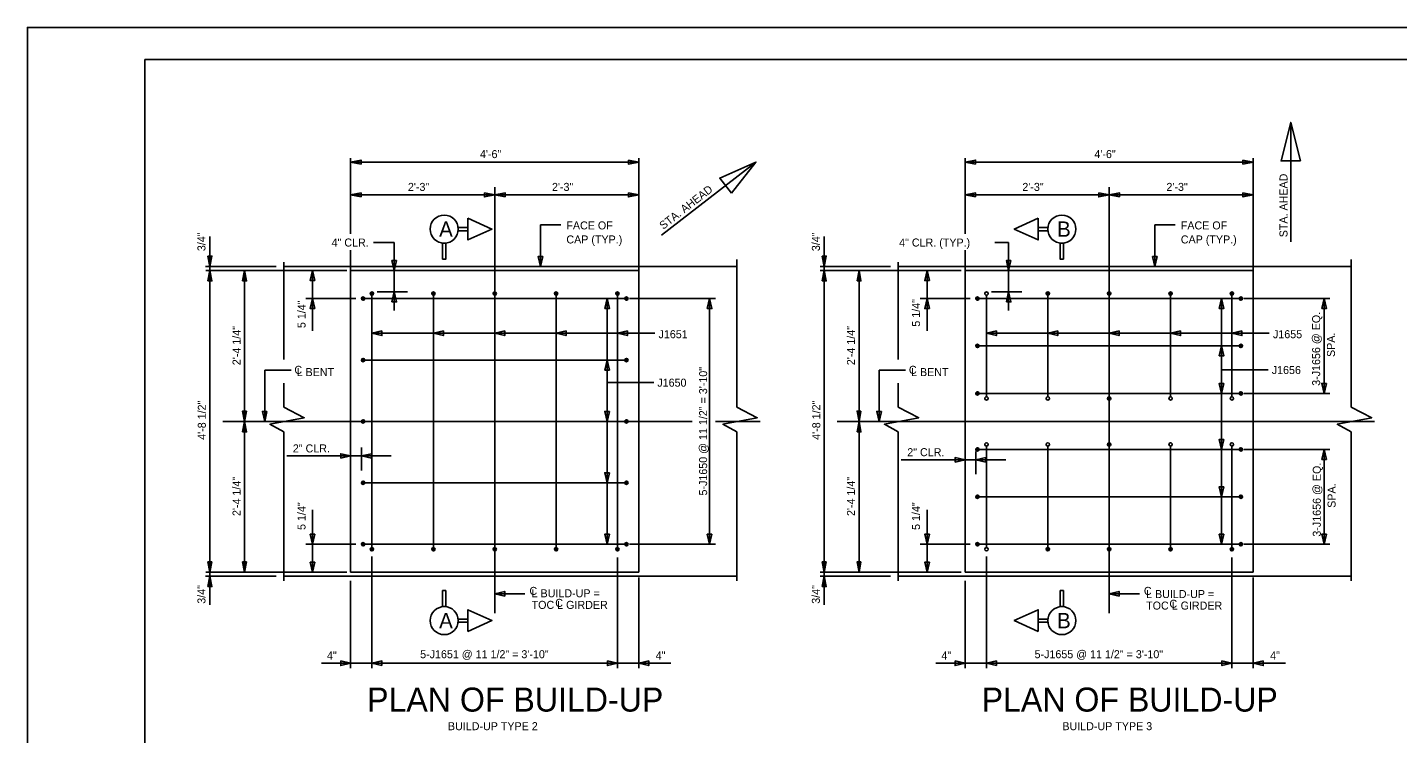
# Model space of a CAD drawing. Extents: x 1970675.2 to 1970711.3, y 796145.2 to 796167.2.
# Drawn here: x 1970675.24 to 1970696.64, y 796156.23 to 796167.25 of the extents above; entities that cross this region are included whole.
import ezdxf

# ---------------------------------------------------------------- set-up
doc = ezdxf.new("R2010")
doc.units = 0
for name, color, linetype in [('BR_AUTO DIMENSION', 7, 'Continuous'), ('BR_BORDER LINES', 7, 'Continuous'), ('BR_CENTER LINES', 7, 'Continuous'), ('BR_CONCRETE', 7, 'Continuous'), ('BR_REBAR', 7, 'Continuous'), ('BR_TEXT', 7, 'Continuous'), ('Default', 7, 'Continuous'), ('Level 31', 7, 'Continuous')]:
    doc.layers.add(name, color=color, linetype=linetype)

msp = doc.modelspace()

# ---------------------------------------------------------------- linework, layer by layer
at = {"layer": 'BR_AUTO DIMENSION'}
for p, q in [((1970694.967, 796165.764), (1970694.967, 796163.9)), ((1970680.285, 796164.025), (1970680.285, 796165.207)), ((1970680.285, 796165.145), (1970684.785, 796165.145)), ((1970684.785, 796163.452), (1970684.785, 796165.207)), ((1970686.613, 796165.146), (1970685.142, 796164.002)), ((1970689.881, 796164.025), (1970689.881, 796165.207)), ((1970689.881, 796165.145), (1970694.381, 796165.145)), ((1970694.381, 796163.452), (1970694.381, 796165.207)), ((1970682.535, 796164.751), (1970682.535, 796164.386)), ((1970692.131, 796164.751), (1970692.131, 796164.386)), ((1970680.285, 796164.632), (1970682.535, 796164.632)), ((1970684.785, 796164.632), (1970682.535, 796164.632)), ((1970689.881, 796164.632), (1970692.131, 796164.632)), ((1970694.381, 796164.632), (1970692.131, 796164.632)), ((1970683.249, 796164.165), (1970683.249, 796163.515)), ((1970683.249, 796164.165), (1970683.566, 796164.165)), ((1970692.845, 796164.165), (1970692.845, 796163.515)), ((1970692.845, 796164.165), (1970693.162, 796164.165)), ((1970678.086, 796163.452), (1970678.086, 796163.985)), ((1970680.965, 796163.89), (1970680.641, 796163.89)), ((1970680.965, 796162.831), (1970680.965, 796163.89)), ((1970687.682, 796163.452), (1970687.682, 796163.985)), ((1970690.561, 796163.89), (1970690.344, 796163.89)), ((1970690.561, 796162.831), (1970690.561, 796163.89)), ((1970680.285, 796163.452), (1970680.285, 796163.771)), ((1970689.881, 796163.452), (1970689.881, 796163.771)), ((1970679.12, 796163.515), (1970678.019, 796163.515)), ((1970680.223, 796163.452), (1970678.023, 796163.452)), ((1970678.086, 796158.744), (1970678.086, 796163.452)), ((1970678.628, 796163.452), (1970678.628, 796161.098)), ((1970679.691, 796163.452), (1970679.691, 796162.513)), ((1970688.716, 796163.515), (1970687.615, 796163.515)), ((1970689.819, 796163.452), (1970687.619, 796163.452)), ((1970687.682, 796158.744), (1970687.682, 796163.452)), ((1970688.224, 796163.452), (1970688.224, 796161.098)), ((1970689.287, 796163.452), (1970689.287, 796162.513)), ((1970680.364, 796163.015), (1970679.583, 796163.015)), ((1970680.697, 796163.119), (1970681.172, 796163.119)), ((1970684.289, 796163.015), (1970684.289, 796159.181)), ((1970684.64, 796163.015), (1970685.983, 796163.015)), ((1970685.891, 796159.181), (1970685.891, 796163.015)), ((1970689.96, 796163.015), (1970689.179, 796163.015)), ((1970690.293, 796163.119), (1970690.768, 796163.119)), ((1970693.885, 796163.015), (1970693.885, 796159.181)), ((1970694.236, 796163.015), (1970695.579, 796163.015)), ((1970695.487, 796161.535), (1970695.487, 796163.015)), ((1970680.618, 796162.474), (1970685.033, 796162.474)), ((1970690.215, 796162.474), (1970694.629, 796162.474)), ((1970678.942, 796161.897), (1970678.942, 796161.098)), ((1970679.354, 796161.897), (1970678.942, 796161.897)), ((1970688.538, 796161.897), (1970688.538, 796161.098)), ((1970688.95, 796161.897), (1970688.538, 796161.897)), ((1970693.885, 796161.902), (1970694.614, 796161.902)), ((1970684.289, 796161.705), (1970685.018, 796161.705)), ((1970694.236, 796161.535), (1970695.579, 796161.535)), ((1970678.571, 796161.098), (1970678.707, 796161.098)), ((1970678.628, 796161.098), (1970678.628, 796158.744)), ((1970688.167, 796161.098), (1970688.303, 796161.098)), ((1970688.224, 796161.098), (1970688.224, 796158.744)), ((1970680.452, 796160.69), (1970680.452, 796160.334)), ((1970690.048, 796160.63), (1970690.048, 796160.275)), ((1970694.236, 796160.66), (1970695.579, 796160.66)), ((1970695.487, 796159.181), (1970695.487, 796160.66)), ((1970680.92, 796160.558), (1970679.286, 796160.558)), ((1970690.516, 796160.498), (1970688.882, 796160.498)), ((1970679.691, 796158.744), (1970679.691, 796159.718)), ((1970689.287, 796158.744), (1970689.287, 796159.718)), ((1970680.364, 796159.181), (1970679.583, 796159.181)), ((1970684.64, 796159.181), (1970685.983, 796159.181)), ((1970689.96, 796159.181), (1970689.179, 796159.181)), ((1970694.236, 796159.181), (1970695.579, 796159.181)), ((1970680.618, 796158.988), (1970680.618, 796157.249)), ((1970684.452, 796158.975), (1970684.452, 796157.249)), ((1970690.215, 796158.988), (1970690.215, 796157.249)), ((1970694.048, 796158.975), (1970694.048, 796157.249)), ((1970679.12, 796158.681), (1970678.019, 796158.681)), ((1970680.223, 796158.744), (1970678.023, 796158.744)), ((1970678.086, 796158.744), (1970678.086, 796158.233)), ((1970688.716, 796158.681), (1970687.615, 796158.681)), ((1970689.819, 796158.744), (1970687.619, 796158.744)), ((1970687.682, 796158.744), (1970687.682, 796158.233)), ((1970680.285, 796158.61), (1970680.285, 796157.249)), ((1970684.785, 796158.661), (1970684.785, 796157.249)), ((1970689.881, 796158.61), (1970689.881, 796157.249)), ((1970694.381, 796158.661), (1970694.381, 796157.249)), ((1970682.535, 796158.408), (1970683.006, 796158.408)), ((1970692.131, 796158.408), (1970692.603, 796158.408)), ((1970679.829, 796157.324), (1970685.287, 796157.324)), ((1970689.425, 796157.324), (1970694.883, 796157.324))]:
    msp.add_line(p, q, dxfattribs=at)
for points in [[(1970680.448, 796165.113), (1970680.285, 796165.145), (1970680.448, 796165.176)], [(1970684.623, 796165.176), (1970684.785, 796165.145), (1970684.623, 796165.113)], [(1970690.044, 796165.113), (1970689.881, 796165.145), (1970690.044, 796165.176)], [(1970694.219, 796165.176), (1970694.381, 796165.145), (1970694.219, 796165.113)], [(1970680.448, 796164.601), (1970680.285, 796164.632), (1970680.448, 796164.664)], [(1970682.373, 796164.664), (1970682.535, 796164.632), (1970682.373, 796164.601)], [(1970682.698, 796164.601), (1970682.535, 796164.632), (1970682.698, 796164.664)], [(1970684.623, 796164.664), (1970684.785, 796164.632), (1970684.623, 796164.601)], [(1970690.044, 796164.601), (1970689.881, 796164.632), (1970690.044, 796164.664)], [(1970691.969, 796164.664), (1970692.131, 796164.632), (1970691.969, 796164.601)], [(1970692.294, 796164.601), (1970692.131, 796164.632), (1970692.294, 796164.664)], [(1970694.219, 796164.664), (1970694.381, 796164.632), (1970694.219, 796164.601)], [(1970678.055, 796163.677), (1970678.086, 796163.515), (1970678.117, 796163.677)], [(1970681.001, 796163.608), (1970680.965, 796163.452), (1970680.929, 796163.608)], [(1970683.285, 796163.671), (1970683.249, 796163.515), (1970683.213, 796163.671)], [(1970687.651, 796163.677), (1970687.682, 796163.515), (1970687.713, 796163.677)], [(1970690.597, 796163.608), (1970690.561, 796163.452), (1970690.525, 796163.608)], [(1970692.881, 796163.671), (1970692.845, 796163.515), (1970692.809, 796163.671)], [(1970678.055, 796163.29), (1970678.086, 796163.452), (1970678.117, 796163.29)], [(1970678.596, 796163.29), (1970678.628, 796163.452), (1970678.659, 796163.29)], [(1970679.727, 796163.296), (1970679.691, 796163.452), (1970679.655, 796163.296)], [(1970687.651, 796163.29), (1970687.682, 796163.452), (1970687.713, 796163.29)], [(1970688.193, 796163.29), (1970688.224, 796163.452), (1970688.255, 796163.29)], [(1970689.323, 796163.296), (1970689.287, 796163.452), (1970689.251, 796163.296)], [(1970679.727, 796162.859), (1970679.691, 796163.015), (1970679.655, 796162.859)], [(1970680.929, 796162.963), (1970680.965, 796163.119), (1970681.001, 796162.963)], [(1970684.253, 796162.859), (1970684.289, 796163.015), (1970684.325, 796162.859)], [(1970685.855, 796162.859), (1970685.891, 796163.015), (1970685.927, 796162.859)], [(1970689.323, 796162.859), (1970689.287, 796163.015), (1970689.251, 796162.859)], [(1970690.525, 796162.963), (1970690.561, 796163.119), (1970690.597, 796162.963)], [(1970693.849, 796162.859), (1970693.885, 796163.015), (1970693.921, 796162.859)], [(1970695.451, 796162.859), (1970695.487, 796163.015), (1970695.523, 796162.859)], [(1970680.774, 796162.51), (1970680.618, 796162.474), (1970680.774, 796162.438)], [(1970681.733, 796162.51), (1970681.577, 796162.474), (1970681.733, 796162.438)], [(1970682.691, 796162.51), (1970682.535, 796162.474), (1970682.691, 796162.438)], [(1970683.649, 796162.51), (1970683.493, 796162.474), (1970683.649, 796162.438)], [(1970684.608, 796162.51), (1970684.452, 796162.474), (1970684.608, 796162.438)], [(1970690.371, 796162.51), (1970690.215, 796162.474), (1970690.371, 796162.438)], [(1970691.329, 796162.51), (1970691.173, 796162.474), (1970691.329, 796162.438)], [(1970692.287, 796162.51), (1970692.131, 796162.474), (1970692.287, 796162.438)], [(1970693.246, 796162.51), (1970693.09, 796162.474), (1970693.246, 796162.438)], [(1970694.204, 796162.51), (1970694.048, 796162.474), (1970694.204, 796162.438)], [(1970693.849, 796162.119), (1970693.885, 796162.275), (1970693.921, 796162.119)], [(1970684.253, 796161.9), (1970684.289, 796162.056), (1970684.325, 796161.9)], [(1970693.921, 796161.691), (1970693.885, 796161.535), (1970693.849, 796161.691)], [(1970695.523, 796161.691), (1970695.487, 796161.535), (1970695.451, 796161.691)], [(1970678.659, 796161.26), (1970678.628, 796161.098), (1970678.596, 796161.26)], [(1970678.978, 796161.254), (1970678.942, 796161.098), (1970678.906, 796161.254)], [(1970684.325, 796161.254), (1970684.289, 796161.098), (1970684.253, 796161.254)], [(1970688.255, 796161.26), (1970688.224, 796161.098), (1970688.193, 796161.26)], [(1970688.574, 796161.254), (1970688.538, 796161.098), (1970688.502, 796161.254)], [(1970678.596, 796160.935), (1970678.628, 796161.098), (1970678.659, 796160.935)], [(1970688.193, 796160.935), (1970688.224, 796161.098), (1970688.255, 796160.935)], [(1970693.921, 796160.816), (1970693.885, 796160.66), (1970693.849, 796160.816)], [(1970680.129, 796160.522), (1970680.285, 796160.558), (1970680.129, 796160.594)], [(1970680.608, 796160.594), (1970680.452, 796160.558), (1970680.608, 796160.522)], [(1970695.451, 796160.504), (1970695.487, 796160.66), (1970695.523, 796160.504)], [(1970689.725, 796160.462), (1970689.881, 796160.498), (1970689.725, 796160.534)], [(1970690.204, 796160.534), (1970690.048, 796160.498), (1970690.204, 796160.462)], [(1970684.325, 796160.296), (1970684.289, 796160.14), (1970684.253, 796160.296)], [(1970693.921, 796160.077), (1970693.885, 796159.921), (1970693.849, 796160.077)], [(1970679.727, 796159.337), (1970679.691, 796159.181), (1970679.655, 796159.337)], [(1970684.325, 796159.337), (1970684.289, 796159.181), (1970684.253, 796159.337)], [(1970685.927, 796159.337), (1970685.891, 796159.181), (1970685.855, 796159.337)], [(1970689.323, 796159.337), (1970689.287, 796159.181), (1970689.251, 796159.337)], [(1970693.921, 796159.337), (1970693.885, 796159.181), (1970693.849, 796159.337)], [(1970695.523, 796159.337), (1970695.487, 796159.181), (1970695.451, 796159.337)], [(1970678.117, 796158.906), (1970678.086, 796158.744), (1970678.055, 796158.906)], [(1970678.659, 796158.906), (1970678.628, 796158.744), (1970678.596, 796158.906)], [(1970679.727, 796158.9), (1970679.691, 796158.744), (1970679.655, 796158.9)], [(1970687.713, 796158.906), (1970687.682, 796158.744), (1970687.651, 796158.906)], [(1970688.255, 796158.906), (1970688.224, 796158.744), (1970688.193, 796158.906)], [(1970689.323, 796158.9), (1970689.287, 796158.744), (1970689.251, 796158.9)], [(1970678.055, 796158.519), (1970678.086, 796158.681), (1970678.117, 796158.519)], [(1970687.651, 796158.519), (1970687.682, 796158.681), (1970687.713, 796158.519)], [(1970682.691, 796158.372), (1970682.535, 796158.408), (1970682.691, 796158.444)], [(1970692.287, 796158.372), (1970692.131, 796158.408), (1970692.287, 796158.444)], [(1970680.129, 796157.36), (1970680.285, 796157.324), (1970680.129, 796157.288)], [(1970680.774, 796157.288), (1970680.618, 796157.324), (1970680.774, 796157.36)], [(1970684.296, 796157.36), (1970684.452, 796157.324), (1970684.296, 796157.288)], [(1970684.941, 796157.36), (1970684.785, 796157.324), (1970684.941, 796157.288)], [(1970689.725, 796157.36), (1970689.881, 796157.324), (1970689.725, 796157.288)], [(1970690.371, 796157.288), (1970690.215, 796157.324), (1970690.371, 796157.36)], [(1970693.892, 796157.36), (1970694.048, 796157.324), (1970693.892, 796157.288)], [(1970694.537, 796157.36), (1970694.381, 796157.324), (1970694.537, 796157.288)]]:
    msp.add_lwpolyline(points, close=True, dxfattribs=at)
at = {"layer": 'BR_BORDER LINES'}
for p in [(1970710.736, 796166.746), (1970677.07, 796145.746)]:
    msp.add_line(p, (1970677.07, 796166.746), dxfattribs=at)
at = {"layer": 'BR_CENTER LINES'}
for p, q in [((1970682.535, 796164.632), (1970682.535, 796158.104)), ((1970692.131, 796164.632), (1970692.131, 796158.104)), ((1970678.286, 796161.098), (1970685.62, 796161.098)), ((1970685.982, 796161.098), (1970686.678, 796161.098)), ((1970687.882, 796161.098), (1970696.274, 796161.098))]:
    msp.add_line(p, q, dxfattribs=at)
at = {"layer": 'BR_CONCRETE'}
for p, q in [((1970679.241, 796163.515), (1970686.315, 796163.515)), ((1970680.285, 796163.452), (1970680.285, 796158.744)), ((1970680.285, 796163.452), (1970684.785, 796163.452)), ((1970684.785, 796163.452), (1970684.785, 796158.744)), ((1970688.837, 796163.515), (1970695.911, 796163.515)), ((1970689.881, 796163.452), (1970694.381, 796163.452)), ((1970689.881, 796163.452), (1970689.881, 796161.098)), ((1970694.381, 796163.452), (1970694.381, 796161.098)), ((1970689.881, 796161.098), (1970689.881, 796158.744)), ((1970689.881, 796161.098), (1970694.381, 796161.098)), ((1970694.381, 796161.098), (1970694.381, 796158.744)), ((1970679.241, 796158.681), (1970686.315, 796158.681)), ((1970680.285, 796158.744), (1970684.785, 796158.744)), ((1970688.837, 796158.681), (1970695.911, 796158.681)), ((1970689.881, 796158.744), (1970694.381, 796158.744))]:
    msp.add_line(p, q, dxfattribs=at)
at = {"layer": 'BR_REBAR'}
for p, q in [((1970680.452, 796163.015), (1970684.618, 796163.015)), ((1970680.618, 796159.077), (1970680.618, 796163.119)), ((1970681.577, 796159.077), (1970681.577, 796163.119)), ((1970682.535, 796159.077), (1970682.535, 796163.119)), ((1970683.493, 796159.077), (1970683.493, 796163.119)), ((1970684.452, 796159.077), (1970684.452, 796163.119)), ((1970690.048, 796163.015), (1970694.215, 796163.015)), ((1970690.215, 796161.483), (1970690.215, 796163.067)), ((1970691.173, 796161.483), (1970691.173, 796163.119)), ((1970692.131, 796161.483), (1970692.131, 796163.119)), ((1970693.09, 796161.483), (1970693.09, 796163.119)), ((1970694.048, 796161.483), (1970694.048, 796163.119)), ((1970690.048, 796162.275), (1970694.215, 796162.275)), ((1970680.452, 796162.056), (1970684.618, 796162.056)), ((1970690.048, 796161.535), (1970694.215, 796161.535)), ((1970680.452, 796161.098), (1970684.618, 796161.098)), ((1970690.048, 796160.66), (1970694.215, 796160.66)), ((1970690.215, 796159.129), (1970690.215, 796160.713)), ((1970691.173, 796159.077), (1970691.173, 796160.712)), ((1970692.131, 796159.077), (1970692.131, 796160.712)), ((1970693.09, 796159.077), (1970693.09, 796160.712)), ((1970694.048, 796159.077), (1970694.048, 796160.712)), ((1970680.452, 796160.14), (1970684.618, 796160.14)), ((1970690.048, 796159.921), (1970694.215, 796159.921)), ((1970680.452, 796159.181), (1970684.618, 796159.181)), ((1970690.048, 796159.181), (1970694.215, 796159.181))]:
    msp.add_line(p, q, dxfattribs=at)
for centre, radius in [((1970680.478, 796163.015), 0.026), ((1970680.618, 796163.093), 0.0261), ((1970681.577, 796163.093), 0.0261), ((1970682.535, 796163.093), 0.0261), ((1970683.493, 796163.093), 0.0261), ((1970684.452, 796163.093), 0.0261), ((1970684.592, 796163.015), 0.026), ((1970690.074, 796163.015), 0.026), ((1970690.215, 796163.093), 0.0261), ((1970691.173, 796163.093), 0.0261), ((1970692.131, 796163.093), 0.0261), ((1970693.09, 796163.093), 0.0261), ((1970694.048, 796163.093), 0.0261), ((1970694.188, 796163.015), 0.026), ((1970690.074, 796162.275), 0.026), ((1970694.188, 796162.275), 0.026), ((1970680.478, 796162.056), 0.026), ((1970684.592, 796162.056), 0.026), ((1970690.074, 796161.535), 0.026), ((1970690.215, 796161.457), 0.0261), ((1970691.173, 796161.457), 0.0261), ((1970692.131, 796161.457), 0.0261), ((1970693.09, 796161.457), 0.0261), ((1970694.048, 796161.457), 0.0261), ((1970694.188, 796161.535), 0.026), ((1970680.478, 796161.098), 0.026), ((1970684.592, 796161.098), 0.026), ((1970690.074, 796160.66), 0.026), ((1970690.215, 796160.739), 0.0261), ((1970691.173, 796160.739), 0.0261), ((1970692.131, 796160.739), 0.0261), ((1970693.09, 796160.739), 0.0261), ((1970694.048, 796160.739), 0.0261), ((1970694.188, 796160.66), 0.026), ((1970680.478, 796160.14), 0.026), ((1970684.592, 796160.14), 0.026), ((1970690.074, 796159.921), 0.026), ((1970694.188, 796159.921), 0.026), ((1970680.478, 796159.181), 0.026), ((1970680.618, 796159.103), 0.0261), ((1970681.577, 796159.103), 0.0261), ((1970682.535, 796159.103), 0.0261), ((1970683.493, 796159.103), 0.0261), ((1970684.452, 796159.103), 0.0261), ((1970684.592, 796159.181), 0.026), ((1970690.074, 796159.181), 0.026), ((1970690.215, 796159.103), 0.0261), ((1970691.173, 796159.103), 0.0261), ((1970692.131, 796159.103), 0.0261), ((1970693.09, 796159.103), 0.0261), ((1970694.048, 796159.103), 0.0261), ((1970694.188, 796159.181), 0.026)]:
    msp.add_circle(centre, radius, dxfattribs=at)
at = {"layer": 'BR_TEXT'}
for points in [[(1970682.115, 796164.267), (1970682.491, 796164.099), (1970682.115, 796163.93)], [(1970691.023, 796164.267), (1970690.648, 796164.099), (1970691.023, 796163.93)], [(1970681.965, 796164.074), (1970682.115, 796164.074), (1970682.115, 796164.124), (1970681.965, 796164.124)], [(1970691.173, 796164.074), (1970691.023, 796164.074), (1970691.023, 796164.124), (1970691.173, 796164.124)], [(1970681.721, 796163.629), (1970681.771, 796163.629), (1970681.771, 796163.88), (1970681.721, 796163.88)], [(1970691.417, 796163.629), (1970691.367, 796163.629), (1970691.367, 796163.88), (1970691.417, 796163.88)], [(1970681.721, 796158.458), (1970681.771, 796158.458), (1970681.771, 796158.208), (1970681.721, 796158.208)], [(1970691.417, 796158.458), (1970691.367, 796158.458), (1970691.367, 796158.208), (1970691.417, 796158.208)], [(1970682.115, 796157.82), (1970682.491, 796157.989), (1970682.115, 796158.158)], [(1970691.023, 796157.82), (1970690.648, 796157.989), (1970691.023, 796158.158)], [(1970681.965, 796158.014), (1970682.115, 796158.014), (1970682.115, 796157.964), (1970681.965, 796157.964)], [(1970691.173, 796158.014), (1970691.023, 796158.014), (1970691.023, 796157.964), (1970691.173, 796157.964)]]:
    msp.add_lwpolyline(points, close=True, dxfattribs=at)
for centre in [(1970681.746, 796164.099), (1970691.392, 796164.099), (1970681.746, 796157.989), (1970691.392, 796157.989)]:
    msp.add_circle(centre, 0.219, dxfattribs=at)
at = {"layer": 'Default'}
for p, q in [((1970686.315, 796163.622), (1970686.315, 796161.319)), ((1970695.911, 796163.622), (1970695.911, 796161.319)), ((1970679.241, 796163.583), (1970679.241, 796162.063)), ((1970688.837, 796163.583), (1970688.837, 796162.063)), ((1970679.241, 796161.692), (1970679.241, 796161.319)), ((1970688.837, 796161.692), (1970688.837, 796161.319)), ((1970679.241, 796160.936), (1970679.241, 796158.609)), ((1970686.315, 796160.936), (1970686.315, 796158.609)), ((1970688.837, 796160.936), (1970688.837, 796158.609)), ((1970695.911, 796160.936), (1970695.911, 796158.609))]:
    msp.add_line(p, q, dxfattribs=at)
for points in [[(1970695.117, 796165.164), (1970694.967, 796165.764), (1970694.817, 796165.164)], [(1970686.232, 796164.659), (1970686.613, 796165.146), (1970686.048, 796164.896)]]:
    msp.add_lwpolyline(points, close=True, dxfattribs=at)
for points in [[(1970679.241, 796160.936), (1970679.024, 796161.054), (1970679.56, 796161.154), (1970679.241, 796161.319)], [(1970686.315, 796160.936), (1970686.098, 796161.054), (1970686.634, 796161.154), (1970686.315, 796161.319)], [(1970688.837, 796160.936), (1970688.62, 796161.054), (1970689.156, 796161.154), (1970688.837, 796161.319)], [(1970695.911, 796160.936), (1970695.694, 796161.054), (1970696.231, 796161.154), (1970695.911, 796161.319)]]:
    msp.add_lwpolyline(points, dxfattribs=at)
at = {"layer": 'Level 31'}
msp.add_lwpolyline([(1970675.236, 796145.246), (1970711.236, 796145.246), (1970711.236, 796167.246), (1970675.236, 796167.246)], close=True, dxfattribs=at)

# ---------------------------------------------------------------- texts
at = {"layer": 'BR_AUTO DIMENSION'}
for s, p in [('4\'-6"', (1970682.304, 796165.207)), ('4\'-6"', (1970691.9, 796165.207)), ('2\'-3"', (1970681.179, 796164.695)), ('2\'-3"', (1970683.429, 796164.695)), ('2\'-3"', (1970690.775, 796164.695)), ('2\'-3"', (1970693.025, 796164.695)), ('FACE OF', (1970683.654, 796164.094)), ('FACE OF', (1970693.25, 796164.094)), ('4" CLR.', (1970679.987, 796163.827)), ('CAP (TYP.)', (1970683.654, 796163.875)), ('4" CLR. (TYP.)', (1970688.851, 796163.827)), ('CAP (TYP.)', (1970693.25, 796163.875)), ('J1651', (1970685.093, 796162.396)), ('J1655', (1970694.689, 796162.396)), ('J1656', (1970694.67, 796161.837)), ('J1650', (1970685.074, 796161.64)), ('2" CLR.', (1970679.382, 796160.614)), ('2" CLR.', (1970688.978, 796160.555)), ('C', (1970683.077, 796158.39)), ('C', (1970683.077, 796158.39)), ('L BUILD-UP = ', (1970683.111, 796158.353)), ('C', (1970692.673, 796158.39)), ('L BUILD-UP = ', (1970692.708, 796158.341)), ('TOC L GIRDER', (1970683.111, 796158.172)), ('C', (1970683.48, 796158.203)), ('TOC L GIRDER', (1970692.708, 796158.161)), ('C', (1970693.072, 796158.189)), ('5-J1651 @ 11 1/2" = 3\'-10"', (1970681.37, 796157.402)), ('5-J1655 @ 11 1/2" = 3\'-10"', (1970690.966, 796157.402)), ('BUILD-UP TYPE 2', (1970681.804, 796156.279)), ('BUILD-UP TYPE 3', (1970691.4, 796156.279))]:
    msp.add_text(s, height=0.125, dxfattribs=at).set_placement(p)
for s, rotation, p in [('STA. AHEAD', 90, (1970694.916, 796163.971)), ('STA. AHEAD', 37.8734, (1970685.167, 796164.086)), ('3-J1656 @ EQ. ', 90, (1970695.426, 796161.653)), ('2\'-4 1/4"', 90, (1970678.565, 796161.975)), ('2\'-4 1/4"', 90, (1970688.161, 796161.975)), ('SPA. ', 90, (1970695.657, 796162.103)), ('5-J1650 @ 11 1/2" = 3\'-10"', 90, (1970685.852, 796159.941)), ('4\'-8 1/2"', 90, (1970678.023, 796160.81)), ('4\'-8 1/2"', 90, (1970687.619, 796160.81)), ('3-J1656 @ EQ. ', 90, (1970695.436, 796159.299)), ('2\'-4 1/4"', 90, (1970678.565, 796159.621)), ('2\'-4 1/4"', 90, (1970688.161, 796159.621)), ('SPA. ', 90, (1970695.667, 796159.749)), ('4"', 360, (1970679.915, 796157.382)), ('4"', 360, (1970685.049, 796157.382)), ('4"', 360, (1970689.511, 796157.382)), ('4"', 360, (1970694.645, 796157.382))]:
    msp.add_text(s, height=0.125, rotation=rotation, dxfattribs=at).set_placement(p)
at = {"layer": 'BR_TEXT'}
for s, rotation, p in [('3/4"', 90, (1970678.017, 796163.755)), ('3/4"', 90, (1970687.613, 796163.755)), ('5 1/4"', 90, (1970679.58, 796162.554)), ('5 1/4"', 90, (1970689.177, 796162.576)), ('C', 360, (1970679.406, 796161.84)), ('L BENT', 360, (1970679.441, 796161.805)), ('C', 360, (1970689.003, 796161.84)), ('L BENT', 360, (1970689.037, 796161.805)), ('5 1/4"', 90, (1970679.58, 796159.404)), ('5 1/4"', 90, (1970689.177, 796159.404)), ('3/4"', 90, (1970678.017, 796158.252)), ('3/4"', 90, (1970687.613, 796158.252))]:
    msp.add_text(s, height=0.125, rotation=rotation, dxfattribs=at).set_placement(p)
for s, height, p in [('A', 0.24, (1970681.666, 796163.979)), ('B', 0.24, (1970691.317, 796163.979)), ('A', 0.24, (1970681.666, 796157.869)), ('B', 0.24, (1970691.317, 796157.869)), ('PLAN OF BUILD-UP', 0.375, (1970680.542, 796156.569)), ('PLAN OF BUILD-UP', 0.375, (1970690.139, 796156.569))]:
    msp.add_text(s, height=height, dxfattribs=at).set_placement(p)

doc.saveas('drawing.dxf')
